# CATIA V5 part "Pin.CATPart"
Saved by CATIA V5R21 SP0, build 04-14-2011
Part number: Pin
Bounding box of the stored display mesh (mm): x -10.997 to 10.997, y 0 to 38, z -10.885 to 10.885
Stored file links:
  D:\CATIA V5R21 E-RESOURCES\CATIA-V5R21\catia-v5r21-Prts\c12_catia_v5r21_prt\c12_catia_v5r21figr_12-54 to 56\Pin.CATPart
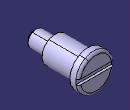
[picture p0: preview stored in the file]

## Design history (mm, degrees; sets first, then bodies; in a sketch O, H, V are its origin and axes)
Body1 (main body)
  Sketch1 on yz-plane, origin (0, 0, 0), H (0, 1, 0), V (0, 0, 1)
    line L1 (0, 0) -> (0, 5)
    line L2 (0, 5) -> (13, 5)
    line L3 (13, 5) -> (13, 8)
    line L4 (13, 8) -> (33, 8)
    line L5 (33, 8) -> (33, 11)
    line L6 (33, 11) -> (38, 11)
    line L7 (38, 11) -> (38, 0)
    point P7 (38, 0)
    line L8 (38, 0) -> (0, 0)
    distance L8 L6 = 11
    distance L4 L8 = 8
    length L8 = 38
    distance L2 L8 = 5
    length L6 = 5
    length L4 = 20
    vertical: L1 V, L3 V, L5 V, L7 V
    horizontal: L2 H, L4 H, L8 H, L6 H
    coincidence: P7 H
  Shaft1: profile Sketch1, axis edge of Sketch1, angle 360
  Chamfer1: length 1.5, angle 45, on 1 edge
  Fillet1: radius 1.5, on 1 edge
  Sketch2 on face of Shaft1, origin (0, 38, 0), H (-1, 0, 0), V (0, 0, 1)
    line L1 (-15.6575, 1.5) -> (20.3727, 1.5)
    line L2 (20.3727, 1.5) -> (20.3727, -1.5)
    line L3 (20.3727, -1.5) -> (-15.6575, -1.5)
    line L4 (-15.6575, -1.5) -> (-15.6575, 1.5)
    distance H L3 = 1.5
    length L4 = 3
    horizontal: L1 H, L3 H
    vertical: L2 V, L4 V
  Pocket1: profile Sketch2, direction (0, -1, 0), length 1.5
